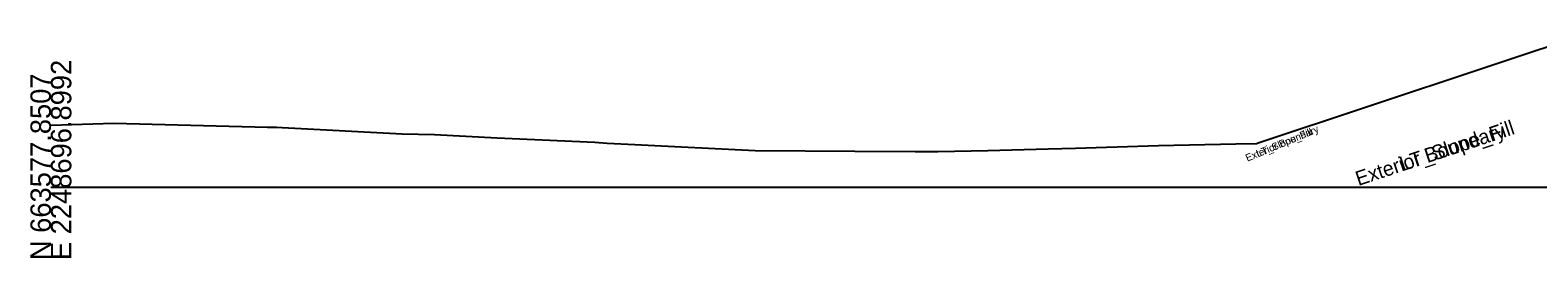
# Model space of a CAD drawing. Extents: x -26 to 2603, y -10 to 9566.
# Drawn here: x 997.2 to 1203.8, y 2490.3 to 2521.6 of the extents above; entities that cross this region are included whole.
import ezdxf

# ---------------------------------------------------------------- set-up
doc = ezdxf.new("R2010")
doc.units = 0
for name, color, linetype in [('Default', 7, 'Continuous'), ('Exist Cross Section Cell', 7, 'Continuous'), ('Exist XS Ground Line', 7, 'Continuous'), ('Scratch_Level_9', 7, 'Continuous')]:
    doc.layers.add(name, color=color, linetype=linetype)

msp = doc.modelspace()

# ---------------------------------------------------------------- linework, layer by layer
at = {"layer": 'Exist Cross Section Cell'}
msp.add_line((1000, 2500), (1300, 2500), dxfattribs=at)
at = {"layer": 'Exist XS Ground Line'}
for p, q in [((1000, 2508.53), (1008.62, 2508.78)), ((1008.62, 2508.78), (1029.68, 2508.24)), ((1029.68, 2508.24), (1030.59, 2508.23)), ((1030.59, 2508.23), (1030.93, 2508.22)), ((1030.93, 2508.22), (1031.68, 2508.19)), ((1031.68, 2508.19), (1048.12, 2507.34)), ((1048.12, 2507.34), (1052.56, 2507.25)), ((1052.56, 2507.25), (1061.14, 2506.79)), ((1061.14, 2506.79), (1074.52, 2506.16)), ((1074.52, 2506.16), (1076.24, 2506.05)), ((1076.24, 2506.05), (1080.03, 2505.85)), ((1080.03, 2505.85), (1096.49, 2505.03)), ((1096.49, 2505.03), (1110.19, 2504.96)), ((1110.19, 2504.96), (1118.46, 2504.91)), ((1118.46, 2504.91), (1121.56, 2504.91)), ((1121.56, 2504.91), (1128.39, 2505.02)), ((1128.39, 2505.02), (1136.67, 2505.26)), ((1136.67, 2505.26), (1140.42, 2505.38)), ((1140.42, 2505.38), (1151.77, 2505.71)), ((1151.77, 2505.71), (1162.39, 2505.96)), ((1162.39, 2505.96), (1165.32, 2505.99))]:
    msp.add_line(p, q, dxfattribs=at)
msp.add_lwpolyline([(1212.03, 2521.55), (1165.32, 2505.99)], dxfattribs=at)

# ---------------------------------------------------------------- texts
at = {"layer": 'Default'}
msp.add_text('-', height=0.0001, dxfattribs=at).set_placement((1000, 2500))
msp.add_text('-', height=0.0001, dxfattribs=at).set_placement((1000, 2500))
msp.add_text('-', height=0.0001, dxfattribs=at).set_placement((1000, 2500))
msp.add_text('-', height=0.0001, dxfattribs=at).set_placement((1000, 2500))
msp.add_text('-', height=0.0001, dxfattribs=at).set_placement((1000, 2500))
at = {"layer": 'Exist Cross Section Cell'}
for s, p in [('E 2248696.8992', (1002.8, 2490)), ('N 663577.8507', (1000, 2490))]:
    msp.add_text(s, height=2.8, rotation=90, dxfattribs=at).set_placement(p)
at = {"layer": 'Scratch_Level_9'}
for s, height, rotation, p in [('Exterior Boundary', 1, 22.5575, (1163.96, 2503.5)), ('Exterior Boundary', 2, 18.4332, (1179.18, 2500.16)), ('Exterior Boundary', 2, 18.4332, (1179.18, 2500.16)), ('LT_Slope_Fill', 2, 18.4332, (1185.23, 2502.18)), ('LT_Slope_Fill', 2, 18.4332, (1185.23, 2502.18)), ('LT_Slope_Fill', 1, 22.5575, (1165.42, 2504.1))]:
    msp.add_text(s, height=height, rotation=rotation, dxfattribs=at).set_placement(p)

doc.saveas('drawing.dxf')
